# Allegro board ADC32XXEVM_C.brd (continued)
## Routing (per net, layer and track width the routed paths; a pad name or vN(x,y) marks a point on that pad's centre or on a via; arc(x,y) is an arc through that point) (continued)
A_INM: length 16.6
  TOP w0.483: R8.1 109.12,63.93 114.53,58.52 119.42,58.52 J2.1
A_INP: length 16.6
  TOP w0.483: J1.1 119.55,74.57 114.12,74.57 108.56,69.01 R4.1
ADCAM: length 23.3
  TOP w0.483: R121.1 v1(70.65,65.96)
  BOTTOM w0.216: v1(70.65,65.96) 71.06,66.37 72.57,66.37 75.35,69.15 75.35,73.22 77.67,75.54 80.1,75.54 81.55,74.09 R101.1
  BOTTOM w0.483: C181.2 84.61,75.01 ; 84.61,75.01 83.69,74.09 R101.1 ; 84.61,75.01 L24.2
ADCAP: length 23.3
  TOP w0.483: R120.2 v1(70.65,67.01)
  BOTTOM w0.216: v1(70.65,67.01) 70.92,66.74 72.41,66.74 74.98,69.3 74.98,73.37 77.52,75.91 80.25,75.91 80.26,75.9 81.51,77.14 R156.2
  BOTTOM w0.483: R156.2 83.67,77.14 84.53,76.28 C181.1 84.71,76.28 L23.2
ADCBM: length 23.3
  TOP w0.483: v1(50.93,65.96) R144.1
  BOTTOM w0.203: R154.2 38.28,74.07 39.65,75.44 40.59,75.44 44.53,71.51 44.53,70.52 48.75,66.29 50.7,66.29 50.93,66.07 v1(50.93,65.96)
  BOTTOM w0.483: R154.2 36.04,74.07 35.26,74.85 C206.1 34.19,75.01 L26.2
ADCBP: length 23.3
  TOP w0.483: v1(50.93,67.01) R141.2
  BOTTOM w0.203: v1(50.93,67.01) 50.57,66.65 48.9,66.65 44.88,70.66 44.88,71.65 40.74,75.79 39.62,75.79 38.3,77.11 R134.1
  BOTTOM w0.483: L27.2 34.24,76.02 C206.2 35.26,76.15 36.22,77.11 R134.1
AINM: length 6.1
  TOP w0.216: R14.2 68.47,66.33 65.23,66.33 65.16,66.27 U1.10
AINP: length 6.1
  TOP w0.216: U1.11 65.16,66.77 65.23,66.7 68.53,66.7 R3.2
AMPAINM: length 19.7
  TOP w0.216: R136.1 105.28,66.07 105.07,66.29 104.85,66.29 104.85,66.28 v1(104.55,65.98)
  BOTTOM w0.216: R97.2 104.33,75.52 104.33,76.21 104.57,76.45 105.23,76.45 106.48,75.21 106.48,71.48 103.42,68.42 103.42,66.71 103.85,66.28 104.25,66.28 v1(104.55,65.98)
  BOTTOM w0.483: R97.2 R96.1 R93.1
AMPAINP: length 19.7
  TOP w0.216: R135.2 105.28,66.87 105.07,66.66 104.84,66.66 v1(104.55,66.95)
  BOTTOM w0.216: v1(104.55,66.95) 104.25,66.65 104,66.65 103.78,66.87 103.78,68.26 106.85,71.32 106.85,75.36 105.39,76.82 104.56,76.82 104.34,77.04 104.34,77.67 103.91,78.11 R98.1
  BOTTOM w0.483: R92.1 101.5,78.11 R98.1
AMPBINM: length 19.7
  TOP w0.216: v1(17.29,66.11) 17.29,66.11 17.01,66.4 16.79,66.4 16.57,66.19 16.57,65.27 R138.1
  BOTTOM w0.216: R133.1 15.75,74.73 15.75,75.51 15.47,75.79 14.86,75.79 14.15,75.08 14.15,74.7 14.26,74.59 14.27,74.59 14.38,74.48 14.38,74.33 14.27,74.22 14.26,74.22 14.15,74.11 14.15,72.94 18.66,68.43 18.66,67.08 17.96,66.38 17.56,66.38 v1(17.29,66.11)
  BOTTOM w0.483: R127.1 R133.1
AMPBINP: length 19.7
  TOP w0.216: v1(17.29,67.07) 17.29,67.06 17.01,66.77 16.79,66.77 16.57,66.99 16.57,67.81 R137.2
  BOTTOM w0.216: v1(17.29,67.07) 17.61,66.75 17.81,66.75 18.29,67.23 18.29,68.28 13.78,72.78 13.78,75.24 14.71,76.16 15.51,76.16 15.72,76.38 15.72,77.32 R132.2
  BOTTOM w0.483: R128.1 R131.1 R132.2
B_INM: length 16.6
  TOP w0.483: R23.1 16.14,68.99 12.93,68.99 7.16,74.75 2.36,74.75 J3.1
B_INP: length 16.6
  TOP w0.483: R138.2 16.21,64.19 12.75,64.19 7.16,58.6 2.34,58.6 J4.1
BINM: length 6.1
  TOP w0.216: R144.2 53.1,66.33 56.34,66.33 56.4,66.27 U1.27
BINP: length 6.1
  TOP w0.216: R141.1 53.04,66.7 56.34,66.7 56.4,66.77 U1.26
CLKINM: length 11.9
  TOP w0.216: R61.1 62.74,72.64 63.07,72.3 63.07,71.81 62.01,70.75 61.84,70.75 60.59,69.51 60.59,68.1 U1.19
  TOP w0.483: T9.4 62.74,74.88 R61.1
CLKINP: length 11.8
  TOP w0.216: U1.18 60.96,68.11 60.96,69.35 61.99,70.38 62.17,70.38 63.36,71.58 63.79,71.58 64.2,71.17 64.8,71.17 R60.2
  TOP w0.483: T9.6 68.97,73.49 66.76,71.28 R60.2
CLOCK_INM: length 7.9
  TOP w0.483: C44.2 76.35,81.28 J10.1
CLOCK_INP: length 8
  TOP w0.483: C43.2 71.57,85 69.22,87.35 J9.1
DA0M: length 53.2
  TOP w0.216: J13.44 67.27,9.61 67.27,11.38 67.5,11.61 67.5,55.37 63.47,59.41 63.47,60.07 63.53,60.14 U1.48
DA0P: length 53.3
  TOP w0.216: U1.47 63.03,60.14 63.1,60.07 63.1,59.25 67.13,55.22 67.13,11.76 66.9,11.53 66.9,9.65 J13.46
DA1M: length 53.2
  TOP w0.216: J13.50 65.77,9.6 65.77,24.02 64.72,25.07 64.72,47.66 65.19,48.13 65.19,50.69 64.72,51.16 64.72,56.07 62.47,58.32 62.47,60.07 62.53,60.14 U1.46
DA1P: length 53.3
  TOP w0.216: U1.45 62.03,60.14 62.1,60.07 62.1,58.17 64.35,55.92 64.35,51 64.82,50.53 64.82,48.29 64.35,47.82 64.35,24.92 65.41,23.86 65.41,9.65 J13.52
DB0M: length 53.3
  TOP w0.216: J13.70 55.77,9.62 55.77,23.46 56.93,24.63 56.93,47.27 57.32,47.65 57.32,50.67 56.93,51.05 56.93,55.94 59.47,58.48 59.47,60.07 59.53,60.14 U1.40
DB0P: length 53.3
  TOP w0.216: U1.39 59.03,60.14 59.1,60.07 59.1,58.63 56.57,56.1 56.57,50.9 56.95,50.52 56.95,47.8 56.57,47.42 56.57,24.78 55.4,23.61 55.4,9.64 J13.72
DB1M: length 53.3
  TOP w0.216: U1.38 58.53,60.14 58.47,60.07 58.47,59.57 54.22,55.32 54.22,9.66 J13.76
DB1P: length 53.2
  TOP w0.216: U1.37 58.03,60.14 58.1,60.07 58.1,59.72 53.85,55.47 53.85,9.59 J13.78
DCLKM: length 53.3
  TOP w0.216: U1.44 61.53,60.14 61.47,60.07 61.47,57.62 62.22,56.87 62.22,52.84 61.93,52.54 61.93,51.01 62.31,50.63 62.31,48.81 62.09,48.6 62.09,46.73 62.51,46.31 62.51,44.9 62.22,44.61 62.22,23.95 64.25,21.92 64.25,9.63 J13.56
DCLKP: length 53.3
  TOP w0.216: J13.58 63.88,9.63 63.88,21.77 61.85,23.8 61.85,44.76 62.14,45.05 62.14,46.16 61.72,46.58 61.72,48.75 61.94,48.96 61.94,50.47 61.56,50.86 61.56,52.7 61.85,52.99 61.85,56.72 61.1,57.47 61.1,60.07 61.03,60.14 U1.43
FCLKM: length 53.3
  TOP w0.216: J13.64 57.26,9.62 57.26,21.34 59.61,23.69 59.61,46 59.3,46.31 59.3,47.73 59.61,48.05 59.61,50.53 59.3,50.85 59.3,52.76 59.61,53.07 59.61,56.79 60.47,57.65 60.47,60.07 60.53,60.14 U1.42
FCLKP: length 53.3
  TOP w0.216: U1.41 60.03,60.14 60.1,60.07 60.1,57.8 59.25,56.95 59.25,53.23 58.93,52.91 58.93,50.69 59.25,50.38 59.25,48.21 58.93,47.89 58.93,46.16 59.25,45.84 59.25,23.85 56.9,21.5 56.9,9.64 J13.66
FPGA_CSEL: length 77.1
  TOP w0.203: J13.115 v1(44.32,4.6)
  TOP w0.254: R70.1 v1(103.5,31.09)
  BOTTOM w0.203: v1(103.5,31.09) 103.5,23.09 89.71,9.3 49.5,9.3 46.86,6.65 46.86,6.07 45.42,4.62 44.35,4.62 v1(44.32,4.6)
FPGA_SCLK: length 74.6
  TOP w0.203: v1(43,4.85) 43,4.24 43.31,3.93 J13.119
  TOP w0.254: R67.1 v1(96.65,31.14)
  BOTTOM w0.203: v1(43,4.85) 43,5.23 43.84,6.07 43.84,6.48 47.88,10.52 47.88,11.4 48.74,12.27 89.46,12.27 96.65,19.46 v1(96.65,31.14)
FPGA_SDI: length 76.4
  TOP w0.203: J13.117 v1(43.81,5.18)
  TOP w0.254: R68.1 v1(101.22,31.17)
  BOTTOM w0.203: v1(43.81,5.18) 45.03,5.18 45.82,5.97 45.82,6.68 49.13,9.99 89.37,9.99 101.22,21.84 v1(101.22,31.17)
FPGA_SDO: length 74.8
  TOP w0.203: J13.113 v1(44.83,5.82)
  TOP w0.254: R69.1 v1(98.93,31.14)
  BOTTOM w0.203: v1(98.93,31.14) 98.93,20.8 89.72,11.59 48.85,11.59 48.34,11.07 48.34,11 48.33,10.99 48.33,10.59 48.34,10.58 48.34,10.26 44.73,6.65 44.73,5.92 v1(44.83,5.82)
FTDI_VCCIO1.8V: length 67.7
  TOP w0.483: v1(40.7,39.26) 39.87,39.26 FB7.1
  TOP w0.508: U2.4 v1(100.09,37.27)
  LYR3_PWR w0.483: v1(100.09,37.27) 95.94,33.12 72.12,33.12 67.55,37.69 66.6,37.69
  LYR3_PWR w0.508: v1(40.7,39.26) 41.12,38.84 51.08,38.84 52.22,37.69 66.6,37.69
PDA: length 6.1
  BOTTOM w0.305: U7.12 93.36,76.87 92.91,77.32 92.91,79.4 R107.2
  BOTTOM w0.483: R107.2 93.55,79.98 R108.2
  BOTTOM w0.508: R108.2 C188.2
PDB: length 5.3
  BOTTOM w0.305: R123.2 27.55,74.56 U10.12
  BOTTOM w0.483: R124.2 30.02,73.53 C200.2 28.65,73.56 R123.2
PDN: length 61.9
  TOP w0.203: U1.31 56.65,64.27 56.18,63.8 v1(55.6,63.8)
  BOTTOM w0.152: v1(55.6,63.8) 55.6,65.51 54.79,66.32 54.79,67.67 55.8,68.68 56.85,68.68 57.1,68.43 58.83,68.43 59.16,68.1 62.08,68.1 62.19,68.21 64.18,68.21 64.34,68.05 64.34,66.62 64.41,66.55 64.41,60.68 65.84,59.26 65.84,58.98 70,54.81 92.96,54.81 94.69,53.09 94.69,50.11 93.6,49.02
RESET: length 57.4
  TOP w0.152: v1(60.2,70.21) 59.53,69.54 U1.21
  BOTTOM w0.152: C168.1 99.31,57.51 70.89,57.51 68.78,59.61 68.78,68.16 66.7,70.25 66.7,70.51 65.74,71.48 63.02,71.48 61.75,70.21 v1(60.2,70.21)
  BOTTOM w0.305: C168.1 99.95,55.75 R58.1 100.1,53.49 SW1.1
SCLK: length 16
  TOP w0.254: R72.1 v1(95.63,32.05)
  BOTTOM w0.254: JP2.2 86.06,32.05 v1(95.63,32.05)
SDATA: length 12.7
  TOP w0.254: R71.1 v1(100.2,32.11)
  BOTTOM w0.254: v1(100.2,32.11) 99.49,32.11 98.04,33.55 92.3,33.55 JP3.2
SDOUT: length 14.3
  TOP w0.254: R73.1 v1(97.92,32.08)
  BOTTOM w0.254: v1(97.92,32.08) 97.21,32.08 96.44,32.84 89.2,32.84 JP5.2
SEN: length 11.1
  TOP w0.254: R74.1 v1(102.49,32.11)
  BOTTOM w0.254: JP4.2 95.53,34.26 99.62,34.26 101.78,32.11 v1(102.49,32.11)
SYSREF_INM: length 7.9
  TOP w0.483: C47.2 48.34,84.97 50.16,86.79 J12.1
SYSREF_INP: length 7.9
  TOP w0.483: C46.2 43.67,81.2 J11.1
SYSREFM: length 11.9
  TOP w0.216: R66.1 55.14,71.2 55.81,71.2 56.24,71.63 56.6,71.63 58.6,69.63 58.6,68.96 58.53,68.9 U1.23
  TOP w0.483: R66.1 54.89,71.09 53.16,71.09 50.96,73.29 T10.4
SYSREFP: length 11.9
  TOP w0.216: R64.2 57.24,72.63 56.87,72.26 56.87,71.88 58.97,69.79 58.97,68.96 59.03,68.9 U1.22
  TOP w0.483: T10.6 55.02,77.47 57.24,75.24 R64.2
U5_SENSE: length 8.5
  TOP w0.203: U5.3 v1(28.14,45.59)
  BOTTOM w0.203: 35.46,45.59 v1(28.14,45.59)
VAMPA: length 10.8
  LYR4_PWR w0.508: 95.71,70.92 95.71,71.78
  BOTTOM w0.305: U7.5 95.86,73.97 v1(95.99,73.84) ; v1(94.79,73.61) 94.86,73.68 U7.7 ; U7.6 95.36,73.68 v1(95.43,73.61) ; U7.8 94.36,73.99 v1(94.21,73.84)
  BOTTOM w0.381: C160.A v1(97.99,71.83) ; C160.A v1(98.37,72.52) ; C160.A v1(97.99,73.15) ; C160.B v1(95.96,73.15) ; C160.B v1(95.55,72.49) ; C160.B v1(95.91,71.88)
  BOTTOM w0.508: D3.2 v1(100.2,80.72) ; R107.1 v1(93.5,82.27) ; 91.41,80.77 v1(91.41,81.46) ; R150.2 v1(89,71.93)
VAMPB: length 9.6
  BOTTOM w0.305: U10.7 25.08,77.66 v1(25.2,77.77) ; v1(24.56,77.77) 24.58,77.75 U10.6 ; v1(23.95,77.62) 24.08,77.49 U10.5 ; U10.8 25.58,77.37 v1(25.81,77.6)
  BOTTOM w0.381: C210.A v1(23.75,79.88) ; C210.A v1(24.23,79.25) ; C210.A v1(23.72,78.61) ; C210.B v1(21.44,79.25) ; C210.B v1(21.97,79.91) ; C210.B v1(21.95,78.64)
  BOTTOM w0.508: v1(19.71,71.96) 19.71,71.25 D4.2 ; R122.2 v1(25.2,79.48) ; R152.2 v1(31.04,79.04) ; R123.1 v1(28.6,71.27)
VCM: length 111.9
  TOP w0.305: v1(57.76,69.01) 58.03,68.74 U1.24
  TOP w0.483: L6.2 v1(47.6,65.81) C11.2 ; L2.2 v1(73.96,65.79) 73.96,65.07 C4.2
  BOTTOM w0.305: R149.1 86.56,71.2 86.56,61.29 85.47,60.2 TP1.1 76.56,60.2 75.49,61.26 75.49,64.26 v1(73.96,65.79) 72.54,64.36 70.05,64.36 69.22,65.2 69.22,69.57 67.31,71.48 67.31,72.29 66.4,73.2 62.41,73.2 61.75,72.54 60.68,72.54 58.29,70.15 58.29,69.55 v1(57.76,69.01) 57.38,69.01 C42.1 55.83,70.56 54.53,70.56 ; 54.53,70.56 53.92,71.17 53.11,71.17 46.07,78.22 46.07,81.85 42.11,85.8 34.09,85.8 31.9,83.62 31.9,81.05 32.39,80.57 v1(32.39,79.12) ; 54.53,70.56 54.53,68.99 52.91,67.36 52.91,65.35 51.77,64.21 49.2,64.21 v1(47.6,65.81)
  BOTTOM w0.508: R104.1 v1(32.39,79.12)
VCM_AMPA: length 6.4
  BOTTOM w0.305: U7.9 93,75.37 C209.1
  BOTTOM w0.483: C209.1 91.14,73.51 R151.1 R150.1 88.98,73.53 R149.2
VCM_AMPB: length 6.7
  BOTTOM w0.305: U10.9 27.06,76.06 C189.1
  BOTTOM w0.483: C189.1 28.75,77.5 R153.1 R152.1 R104.2
N16255310: length 6.4
  TOP w0.483: T1.5 v1(97.87,66.47) T1.2
  BOTTOM w0.508: v1(97.87,66.47) 97.92,66.52 C5.2
N16255380: length 4.5
  TOP w0.483: T2.4 T1.6
N16255412: length 4.5
  TOP w0.483: T2.6 T1.4
N16255546: length 6.3
  TOP w0.483: T2.5 v1(87.88,66.47) T2.2
  BOTTOM w0.483: C6.2 v1(87.88,66.47)
N16275326: length 6.2
  TOP w0.483: T3.5 v1(23.64,66.52) T3.2
  BOTTOM w0.483: C12.2 v1(23.64,66.52)
N16275406: length 3
  TOP w0.483: T4.1 36.62,63.93 C14.1
N16275410: length 4.5
  TOP w0.483: T3.4 26.48,64 T4.6
N16275430: length 4.5
  TOP w0.483: T3.6 26.48,69.08 T4.4
N16275564: length 6.3
  TOP w0.483: T4.2 33.71,66.54 v1(33.7,66.53) 33.69,66.54 T4.5
  BOTTOM w0.483: C13.2 v1(33.7,66.53)
N17995731: length 3
  TOP w0.483: C7.1 85.03,63.94 T2.3
N18036747: length 3.6
  TOP w0.483: R4.2 T1.3
N18037025: length 3.6
  TOP w0.483: R8.2 T1.1
N18037341: length 3.5
  TOP w0.483: R20.1 20.67,64.03 20.79,63.91 T3.3
N18145356: length 2.2
  TOP w0.483: R62.1 72.95,77.88 72.92,77.88
N18145361: length 2.2
  TOP w0.483: C43.1 69.32,81.55 T9.3
N18152532: length 3
  TOP w0.483: C1.1 T2.1
N18152657: length 3
  TOP w0.483: C8.1 T4.3
N18154317: length 68.6
  TOP w0.152: U1.13 63.53,68.41 63.8,68.68 v1(64.11,68.68)
  BOTTOM w0.152: JP2.1 84.33,40.89 90.4,40.89 95.94,46.43 95.94,52.78 93.37,55.35 70.26,55.35 67.34,58.27 67.34,63.28 67.44,63.39 67.44,66.27 66.7,67.01 66.7,67.59 66.17,68.12 65.68,68.12 65.1,68.71 63.88,68.71 v1(64.11,68.68)
N18154319: length 67.8
  TOP w0.152: U1.16 61.98,68.1 61.98,68.71 63.07,69.8 64.34,69.8 v1(64.72,69.42)
  BOTTOM w0.152: v1(64.72,69.42) 64.92,69.42 65.76,68.58 66.27,68.58 67.06,67.79 67.06,67.26 67.77,66.55 67.77,58.67 70.51,55.93 93.45,55.93 96.44,52.93 96.44,46.23 90.3,40.08 87.45,40.08 JP5.1
N18154320: length 66.4
  TOP w0.152: U1.15 62.53,68.83 63.17,69.47 63.98,69.47 64.54,68.91 65.53,68.91 v1(66.04,69.42)
  BOTTOM w0.152: v1(66.04,69.42) 66.95,69.42 68.45,67.92 68.45,59.31 70.84,56.92 93.65,56.92 97.49,53.09 97.49,45.39 93.73,41.63 JP4.1
  BOTTOM w0.254: 95.86,38.61 JP4.1
N18154541: length 64.7
  TOP w0.152: v1(63.4,68.99) 63.27,68.99 63.03,68.75 U1.14
  BOTTOM w0.152: v1(63.4,68.99) 64.29,69.88 65.32,69.88 65.58,69.61 65.58,69.23 65.85,68.96 66.83,68.96 68.12,67.67 68.12,58.98 70.74,56.36 93.57,56.36 96.95,52.98 96.95,45.77 JP3.1
N18158256: length 7
  TOP w0.381: C51.1 103.38,46.34 C50.1 103.34,45.04 U2.20
  TOP w1.016: FB1.1 103.89,46.88 C51.1
N18158298: length 3.1
  TOP w0.254: R73.2 99.44,33.27 U2.3
N18158304: length 3.5
  TOP w0.254: U2.1 98.14,34.26 R72.2
N18158332: length 10.9
  TOP w0.483: J14.2 110.27,38.65 C53.1 107.98,38.48 105.94,40.52 U2.16
N18158362: length 2.6
  TOP w0.483: C54.1 105.29,44.84 U2.17
N18158372: length 9.3
  TOP w0.483: U2.15 106.59,41.27 108.15,39.7 C52.1 110.36,39.45 J14.3
N18158488: length 3.1
  TOP w0.254: R71.2 100.74,33.25 U2.5
N18172592: length 3.5
  TOP w0.483: 20.81,69.11 R25.1
N18176897: length 4.2
  TOP w0.483: R9.1 76.07,64.95 C3.2 ; C3.2 L2.1 ; C3.2 R5.2
N18176915: length 2.4
  TOP w0.483: R6.2 C2.1 72.59,66.98 L3.2
N18176926: length 2.4
  TOP w0.483: L3.1 72.49,65.96 C2.2 R10.1
N18176961: length 3.7
  TOP w0.483: R3.1 R6.1 R2.2
N18176965: length 3.7
  TOP w0.483: R14.1 R10.2 R13.2
N18176992: length 4
  TOP w0.483: R2.1 R5.1 R1.2 L1.1
N18176994: length 3.9
  TOP w0.483: R13.1 R9.2 77.29,63.93 R12.2 77.27,63.96 L4.1
N18177028: length 4
  TOP w0.483: C1.2 81.02,69.04 R1.1 L1.2
N18177046: length 3.9
  TOP w0.483: L4.2 78.28,63.96 R12.1 C7.2
N18177748: length 4.2
  TOP w0.483: C10.2 45.49,68.02 R21.2 ; C10.2 L6.1 ; C10.2 R22.1
N18177758: length 2.4
  TOP w0.483: L7.2 49.07,67.01 C9.1 R19.2
N18177777: length 2.4
  TOP w0.483: R24.1 C9.2 48.97,65.99 L7.1
N18177812: length 3.7
  TOP w0.483: R139.1 R19.1 R16.2
N18177816: length 3.7
  TOP w0.483: R142.1 R24.2 R27.2
N18177835: length 3.9
  TOP w0.483: R16.1 R21.1 45.46,69.03 R15.2 44.27,67.85 L5.1
N18177837: length 4
  TOP w0.483: L8.1 R26.2 R22.2 R27.1
N18177879: length 3.9
  TOP w0.483: C8.2 43.21,69.08 R15.1 43.28,69.01 L5.2
N18177897: length 3.9
  TOP w0.483: L8.2 R26.1 C14.2
N18182829: length 2.2
  TOP w0.483: 49.08,82.94 T10.1
N18182834: length 2.2
  TOP w0.483: C46.1 45.49,79.35 T10.3
N18184820: length 3.5
  TOP w0.305: U4.1 36.09,24.89 R80.1 37.34,23.88 R76.2
N18184826: length 4.3
  TOP w0.305: R77.2 R81.1 38.22,26.67 U4.3
N18184858: length 3.8
  TOP w0.305: L17.1 30.57,26.17 U4.7
N18184878: length 1
  TOP w0.508: R79.1 v1(38.23,31.37) ; R78.1 v1(38.23,30.23)
  vias: v1(31.24,32.38) v1(31.24,31.75) v1(31.24,31.12) v1(31.24,30.48) v1(31.24,29.84) v1(32,29.84)
N18184911: length 0.8
  TOP w0.305: U4.4 35.55,27.17 35.94,27.56
N18184929: length 1.3
  TOP w0.508: FB7.2 v1(33.73,40.41)
N18185106: length 2.7
  TOP w0.305: U5.14 v1(19.88,44.94)
  BOTTOM w0.508: v1(19.88,44.94) 19.96,44.86 C74.1
N18185155: length 1.7
  TOP w0.305: U5.12 v1(20.72,46.24)
  BOTTOM w0.508: v1(20.72,46.24) 20.86,46.1 R84.2
N18185175: length 1.9
  TOP w0.305: U5.11 20.95,46.89 v1(20.7,47.14)
  BOTTOM w0.508: v1(20.7,47.14) 20.8,47.24 R85.2
N18185416: length 8.1
  BOTTOM w0.508: TP8.1 40.92,33.88 R83.1 38.61,35.69 38.02,35.1 36.32,35.1 35.16,36.26 U6.1
N18185709: length 6.1
  TOP w0.508: Q1.4 21.59,27.3 20.32,28.57 20.32,31.12 19.36,32.07 U3.4
N18185817: length 2.9
  TOP w0.508: R75.2 21.97,29.21
N18186843: length 3.4
  TOP w0.305: U2.11 104.64,33.9 R74.2
N18187243: length 5.2
  TOP w0.305: J14.4 111.87,40.25 111.35,40.77 111.35,41.73 110.67,42.42 110.13,42.42 R86.1
N18187932: length 2.3
  BOTTOM w0.254: R87.2 106.58,53.52 SW1.2
N18195117: length 2.1
  TOP w0.635: 63.8,72.39 R61.2 ; 63.8,72.39 R60.1 ; 63.8,72.39 64.56,73.15 C45.1
N18195272: length 6.3
  TOP w0.508: T9.2 v1(69.18,77.74) T9.5
  BOTTOM w0.508: C173.1 69.18,77.67 v1(69.18,77.74)
N18195497: length 2.1
  TOP w0.635: 56.15,72.35 55.39,73.1 C48.1 ; 56.15,72.35 R64.1 ; 56.15,72.35 R66.2
N18195560: length 6.5
  TOP w0.508: T10.2 v1(50.75,77.68) 52.76,75.67
  BOTTOM w0.508: v1(50.75,77.68) 51.38,78.31 C174.1
N18236051: length 3.3
  BOTTOM w0.483: R109.2 90.17,76.3 C180.1 89.1,76.28 L23.1
N18236057: length 3.3
  BOTTOM w0.483: R110.2 90.42,75.29 C180.2 87.55,75.29 L24.1
N18238916: length 3.6
  BOTTOM w0.508: FB8.1 89.23,79.2 R106.1 91.41,77.93 C187.1
N18248026: length 2.3
  BOTTOM w0.305: U7.10 92.03,75.87 R110.1
N18248246: length 2.1
  BOTTOM w0.305: U7.11 91.67,76.37 R109.1
N18248498: length 4.5
  BOTTOM w0.305: R93.2 100.48,75.41 99.72,76.17 R95.2 98.96,75.87 U7.3
N18248506: length 2.6
  BOTTOM w0.305: R95.1 99.05,75.37 U7.4
N18248596: length 6.3
  BOTTOM w0.305: D3.3 100.46,78.24 R92.2 99.52,77.19 R94.2 98.45,76.37 U7.2
N18248639: length 3.1
  BOTTOM w0.305: R94.1 99.01,78.21 97.68,76.87 U7.1
N18255095: length 2.5
  TOP w0.305: C195.1 17.9,50.05 U8.14
N18255144: length 2.4
  TOP w0.305: R114.2 16.6,50.12 U8.12
N18255168: length 2.7
  TOP w0.305: R113.2 15.95,50.74 U8.11
N18255172: length 2.1
  TOP w0.305: U8.10 13.41,53.74 R116.2
N18255251: length 2.1
  TOP w0.508: U9.1 25.81,57.45 R115.1
N18258500: length 1.8
  TOP w0.305: R117.2 12.82,54.39 U8.9
N18258503: length 2.1
  TOP w0.305: U8.8 13.44,55.04 R118.2
N18258506: length 2.1
  TOP w0.305: R119.2 13.41,56.34 U8.6
N18271567: length 3
  BOTTOM w0.508: FB9.1 C199.1 R122.1
N18273924: length 3.1
  BOTTOM w0.483: R125.2 29.59,75.01 C205.1 32.41,75.01 32.51,74.9
N18273934: length 3.1
  BOTTOM w0.483: R126.2 29.64,76.02 C205.2 32.36,76.02 32.51,76.17
N18274097: length 2.3
  BOTTOM w0.305: U10.10 27.86,75.56 R126.1
N18274103: length 2.1
  BOTTOM w0.305: R125.1 28.32,75.06 U10.11
N18274115: length 4.6
  BOTTOM w0.305: U10.3 22.23,75.56 21.11,76.68 R130.2 20.52,76.68 R128.2
N18274119: length 3.2
  BOTTOM w0.305: R130.1 20.83,77.7 22.47,76.06 U10.4
N18274129: length 5.9
  BOTTOM w0.305: D4.3 20.64,73.24 R127.2 20.52,75.39 R129.2 21.31,75.39 21.64,75.06 U10.2
N18274135: length 2.6
  BOTTOM w0.305: R129.1 20.87,74.56 U10.1
N18283030: length 1.6
  BOTTOM w0.508: C207.1 102.59,72.44 SJP1.3
N18283930: length 1.8
  BOTTOM w0.483: R97.1 103.96,72.49 SJP1.2
N18284096: length 1.5
  BOTTOM w0.508: C208.1 18.97,80.7 SJP2.3
N18284104: length 2
  BOTTOM w0.508: SJP2.2 16.1,80.64 R132.1
N18358536: length 2.1
  BOTTOM w0.483: R155.1 36.42,75.59 ; 36.42,75.59 R134.2 ; 36.42,75.59 R154.1
N18359182: length 2.1
  BOTTOM w0.483: R101.2 83.41,75.62 ; 83.41,75.62 R156.1 ; 83.41,75.62 R157.1

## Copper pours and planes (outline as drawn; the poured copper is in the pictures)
1.8V on BOTTOM: 15.88,36.4 15.88,34.29 16.51,33.66 33.27,33.66 33.27,36.4
2.8V_IN on TOP: 16.26,39.88 16.26,45.85 22.35,45.85 22.35,43.56 23.24,43.56 23.24,42.16 20.96,39.88
5.0V_IN on TOP (solid shape): 20,23.14 16.19,23.14 16.19,27.66 20,27.66
5.0V_IN on TOP: 20.07,27.74 20.07,17.78 15.72,17.78 11.05,22.45 11.05,33.66 17.78,33.66 17.78,27.74
5.0V_IN on BOTTOM: 3.18,27.94 3.18,43.18 13.97,43.18 13.97,34.14 20.32,27.79 20.32,17.78 14.61,17.78 13.34,19.05 13.34,19.68 10.79,22.23 8.89,22.23
5.0V_IN on LYR2_GND, LYR3_PWR, LYR4_PWR, LYR5_GND: 16.89,27.81 16.89,22.99 20.07,22.99 20.07,27.81
5VIN on TOP: 31.29,20.7 31.29,23.39 32.84,24.94 32.84,25.55 33.02,25.73 33.73,25.73 33.78,25.68 33.78,23.32 32.97,22.5 32.97,20.7
5VIN on TOP: 24.89,21.97 24.89,24.13 25.53,24.13 25.53,25.91 25.65,25.91 25.65,29.59 27.94,29.59 27.94,27.3 26.8,27.3 26.8,21.97
5VIN on BOTTOM, LYR2_GND, LYR3_PWR, LYR5_GND: 25.91,29.21 25.91,27.3 28.19,27.3 28.19,29.21
5VIN on LYR4_PWR: 5.08,17.78 5.08,40 23.5,40 26.67,43.18 26.67,46.99 25.65,48.01 16.97,48.01 16.97,52.7 19.05,52.7 20.32,53.97 22.48,53.97 22.48,53.34 24.77,53.34 24.77,53.97 25.4,54.61 27.94,54.61 34.29,48.26 34.32,40 97.79,40 97.79,50.8 116.84,50.8 116.84,17.78
+VCC on TOP: 21.23,84.48 21.23,81.91 23.95,81.91 23.95,84.48
+VCC on TOP: 90.65,84.53 90.65,82.3 90.58,82.22 88.21,82.22 88.21,84.53
+VCC on BOTTOM: 21.21,84.43 21.21,81.99 23.62,81.99 24.16,82.52 25.25,82.52 25.25,84.43
+VCC on BOTTOM: 20.83,55.63 20.83,54.86 21.84,53.85 24.26,53.85 24.26,54.61 23.24,55.63
+VCC on BOTTOM: 90.78,82.45 90.78,84.58 88.29,84.58 88.29,80.85 89.94,80.85 89.94,81.61
+VCC on LYR2_GND, LYR3_PWR, LYR5_GND: 20.96,84.45 20.96,81.91 23.75,81.91 23.75,84.45
+VCC on LYR2_GND, LYR3_PWR, LYR5_GND: 90.45,85.9 90.45,83.67 90.37,83.59 88.01,83.59 88.01,85.9
+VCC on LYR4_PWR: 92.07,84.12 89.87,81.91 88.16,81.91 87.58,82.5 87.58,85.19 86.87,85.9 78.49,85.9 78.33,85.75 78.33,79.22 42.42,79.22 42.42,84.53 41.1,85.85 33.38,85.85 31.75,84.45 31.75,81.28 20.96,81.28 15.88,76.2 15.88,67.69 17.91,65.66 17.91,57.78 2.54,57.78 2.54,95.88 92.07,95.88
AVDD1.8V on TOP, LYR2_GND, LYR3_PWR, LYR5_GND: 41.2,54.69 44.48,54.69 44.63,54.53 44.63,52.1 44.42,51.89 42.77,51.89 42.67,51.99 42.67,53.16 42.37,53.47 41.25,53.47 41.07,53.64 41.07,54.56
AVDD1.8V on BOTTOM: 41.33,51.71 41.33,54.71 44.6,54.71 44.6,51.71
AVDD1.8V on LYR4_PWR: 35.81,50.8 35.81,74.8 69.22,74.8 69.22,63.37 65.76,63.37 65.38,63.75 47.37,63.75 46.99,63.37 46.99,50.8
DVDD1.8V on TOP, LYR2_GND, LYR4_PWR, LYR5_GND: 42.37,48.56 44.37,48.56 44.68,48.26 44.68,45.77 44.48,45.57 41.58,45.57 41.3,45.85 41.3,46.28 41.5,46.48 42.19,46.48 42.29,46.58 42.29,48.49
DVDD1.8V on BOTTOM: 41.38,48.46 41.38,45.62 44.6,45.62 44.6,48.46
DVDD1.8V on LYR3_PWR: 39.37,40.64 39.37,49.53 47.62,49.53 47.62,63.32 65.35,63.32 66.57,62.1 116.84,62.1 116.84,51.44 97.16,51.44 97.16,40.64
GND on TOP: 0.25,96.95 0.25,12.95 23.11,12.95 23.11,0.25 98.81,0.25 98.81,12.95 121.67,12.95 121.67,96.95 ; 18 cut-outs
GND on BOTTOM: 0.25,96.95 0.25,12.95 23.11,12.95 23.11,0.25 98.81,0.25 98.81,12.95 121.67,12.95 121.67,96.95 ; 3 cut-outs
GND on LYR2_GND, LYR3_PWR, LYR4_PWR, LYR5_GND: 0.25,96.95 0.25,12.95 23.11,12.95 23.11,0.25 98.81,0.25 98.81,12.95 121.67,12.95 121.67,96.95
CLKINM on TOP (solid shape): 66.63,77.88 66.99,77.88 67.35,78.24 67.44,78.33 67.94,77.83 67.28,77.16 65.91,77.16 65.37,76.62 64.48,77.52 65.5,78.55 65.54,78.55 65.75,78.76
CLKINP on TOP (solid shape): 69.77,76 69.32,75.55 69.32,75.19 70.21,74.31 68.95,73.05 68.07,73.93 68.61,74.47 68.61,75.83 69.27,76.5
SYSREFM on TOP (solid shape): 50.75,76.35 51.32,75.78 51.32,74.41 51.86,73.87 50.96,72.98 49.94,74 49.94,74.04 49.72,74.25 50.6,75.13 50.6,75.49 50.24,75.85 50.15,75.94 50.66,76.44
SYSREFP on TOP (solid shape): 55.43,77.45 55.24,77.25 54.56,76.57 54.02,77.11 52.65,77.11 51.99,77.77 52.49,78.27 52.94,77.83 53.3,77.83 54,78.53 54.18,78.71
U5_SENSE on BOTTOM: 36.53,37.9 36.53,42.82 35.31,44.04 35.31,53.59 39.12,53.59 39.12,38.25 38.76,37.9
VAMPA on LYR4_PWR: 102.64,79.6 102.64,72.42 100.84,70.61 87.53,70.61 87.53,78.51 91.82,82.8 99.44,82.8
VAMPB on LYR4_PWR: 33.53,70.87 17.4,70.87 17.4,76.33 21.72,80.64 30.15,80.64 33.53,77.27
N16255310 on TOP (solid shape): 96.27,66.85 97.16,66.85 97.16,66.09 96.27,66.09 96.01,65.84 95.83,65.84 95.83,66.09 94.49,66.09 94.49,66.85 95.83,66.85 95.83,67.11 96.01,67.11
N16255310 on TOP (solid shape): 100.76,67.08 100.76,66.85 101.35,66.85 101.35,66.09 100.86,66.09 100.86,65.84 99.82,65.84 99.57,66.09 98.68,66.09 98.68,66.85 99.57,66.85 99.82,67.11 100.74,67.11
N16255380 on TOP (solid shape): 97.16,64.8 96.52,64.8 96.27,64.54 96.27,63.3 94.49,63.3 94.49,64.54 95.25,64.54 96.22,65.51 97.16,65.51
N16255380 on TOP (solid shape): 90.49,64.54 91.25,64.54 91.25,63.27 89.8,63.27 89.78,63.3 89.47,63.3 89.47,64.54 89.22,64.8 88.59,64.8 88.59,65.51 89.52,65.51
N16255412 on TOP (solid shape): 91.25,68.4 90.49,68.4 89.52,67.44 88.59,67.44 88.59,68.15 89.22,68.15 89.47,68.4 89.47,69.65 91.25,69.65
N16255412 on TOP (solid shape): 95.96,69.65 96.27,69.65 96.27,68.4 96.52,68.15 97.16,68.15 97.16,67.44 96.22,67.44 95.25,68.4 94.49,68.4 94.49,69.67 95.94,69.67
N16255546 on TOP (solid shape): 89.91,66.85 91.25,66.85 91.25,66.09 89.91,66.09 89.91,65.84 89.73,65.84 89.47,66.09 88.59,66.09 88.59,66.85 89.47,66.85 89.73,67.11 89.91,67.11
N16255546 on TOP (solid shape): 86.17,66.85 87.06,66.85 87.06,66.09 86.17,66.09 85.92,65.84 85,65.84 84.98,65.86 84.98,66.09 84.39,66.09 84.39,66.85 84.88,66.85 84.88,67.11 85.92,67.11
N16275326 on TOP (solid shape): 25.74,66.9 27.09,66.9 27.09,66.14 25.74,66.14 25.74,65.88 25.57,65.88 25.31,66.14 24.42,66.14 24.42,66.9 25.31,66.9 25.57,67.15 25.74,67.15
N16275326 on TOP (solid shape): 22.01,66.9 22.9,66.9 22.9,66.14 22.01,66.14 21.76,65.88 20.84,65.88 20.82,65.91 20.82,66.14 20.23,66.14 20.23,66.9 20.71,66.9 20.71,67.15 21.76,67.15
N16275406 on TOP (solid shape): 36.45,64.61 37.13,64.61 37.16,64.58 37.16,63.39 35.41,63.39 35.41,64.64 35.15,64.89 34.52,64.89 34.52,65.6 35.46,65.6
N16275410 on TOP (solid shape): 32.99,64.89 32.36,64.89 32.1,64.64 32.1,63.39 30.33,63.39 30.33,64.64 31.09,64.64 32.05,65.6 32.99,65.6
N16275410 on TOP (solid shape): 26.33,64.61 27.09,64.61 27.09,63.34 25.64,63.34 25.62,63.37 25.31,63.37 25.31,64.61 25.06,64.87 24.42,64.87 24.42,65.58 25.36,65.58
N16275430 on TOP (solid shape): 27.09,68.42 26.33,68.42 25.36,67.46 24.42,67.46 24.42,68.17 25.06,68.17 25.31,68.42 25.31,69.67 27.09,69.67
N16275430 on TOP (solid shape): 31.8,69.69 32.1,69.69 32.1,68.45 32.36,68.19 32.99,68.19 32.99,67.48 32.05,67.48 31.09,68.45 30.33,68.45 30.33,69.72 31.77,69.72
N16275564 on TOP (solid shape): 32.1,66.92 32.99,66.92 32.99,66.16 32.1,66.16 31.85,65.91 31.67,65.91 31.67,66.16 30.33,66.16 30.33,66.92 31.67,66.92 31.67,67.18 31.85,67.18
N16275564 on TOP (solid shape): 36.6,67.15 36.6,66.92 37.18,66.92 37.18,66.16 36.7,66.16 36.7,65.91 35.66,65.91 35.41,66.16 34.52,66.16 34.52,66.92 35.41,66.92 35.66,67.18 36.57,67.18
N17995731 on TOP (solid shape): 87.06,64.82 86.43,64.82 86.17,64.57 86.17,63.32 84.42,63.32 84.42,64.54 85.13,64.54 86.12,65.53 87.06,65.53
N18036747 on TOP (solid shape): 101.32,68.43 100.61,68.43 99.62,67.44 98.68,67.44 98.68,68.15 99.31,68.15 99.57,68.4 99.57,69.65 101.32,69.65
N18037025 on TOP (solid shape): 100.61,64.52 101.3,64.52 101.32,64.49 101.32,63.3 99.57,63.3 99.57,64.54 99.31,64.8 98.68,64.8 98.68,65.51 99.62,65.51
N18037341 on TOP (solid shape): 22.9,64.87 22.26,64.87 22.01,64.61 22.01,63.37 20.26,63.37 20.26,64.59 20.97,64.59 21.96,65.58 22.9,65.58
N18145356 on TOP (solid shape): 73.78,77.88 72.54,76.64 72.29,76.89 71.66,77.52 71.3,77.52 70.85,77.07 70.35,77.58 71.01,78.24 72.41,78.24 72.9,78.73 72.94,78.73
N18145361 on TOP (solid shape): 70.19,81.47 69.68,80.97 69.68,79.57 69.02,78.91 68.52,79.41 68.97,79.86 68.97,80.22 68.09,81.1 69.32,82.34
N18152532 on TOP (solid shape): 86.17,68.4 86.43,68.15 87.06,68.15 87.06,67.44 86.12,67.44 85.13,68.43 84.44,68.43 84.42,68.45 84.42,69.65 86.17,69.65
N18152657 on TOP (solid shape): 37.16,68.47 36.45,68.47 35.46,67.48 34.52,67.48 34.52,68.19 35.15,68.19 35.41,68.45 35.41,69.69 37.16,69.69
N18172592 on TOP (solid shape): 22.01,68.42 22.26,68.17 22.9,68.17 22.9,67.46 21.96,67.46 20.97,68.45 20.28,68.45 20.26,68.47 20.26,69.67 22.01,69.67
N18182829 on TOP (solid shape): 51.84,81.04 51.59,80.79 50.96,80.16 50.96,79.8 51.41,79.35 50.91,78.85 50.24,79.51 50.24,80.91 49.76,81.4 49.76,81.44 50.6,82.28
N18182834 on TOP (solid shape): 47.51,78.18 48.92,78.18 49.58,77.52 49.08,77.02 48.63,77.47 48.27,77.47 47.39,76.59 46.15,77.83 47.01,78.69
N18184858 on TOP: 28.19,25.02 28.19,26.29 33.66,26.29 33.66,26.04 32.64,26.04 31.75,25.15 31.75,25.02
N18184878 on TOP: 28.45,27.05 28.45,29.46 28.7,29.72 28.7,32.77 32.51,32.77 32.51,29.72 33.76,29.72 33.76,27.05
N18184878 on LYR3_PWR: 38.73,32.77 38.73,29.46 30.48,29.46 30.48,32.77
N18184911 on TOP: 35.08,27.18 35.08,27.94 36.07,27.94 36.32,28.19 36.32,31.75 37.08,31.75 37.08,27.43 36.83,27.18
N18184929 on BOTTOM: 35.56,37.16 35.56,41.15 33.91,42.8 33.91,42.82 30.12,42.82 29.46,42.16 29.46,37.16
N18184992 on TOP: 20.93,17.91 20.93,26.42 23.06,26.42 23.06,21.08 26.54,21.08 26.54,17.91
N18185086 on TOP: 32.39,39.88 32.39,41.66 29.97,41.66 29.72,41.91 29.72,44.58 26.42,44.58 26.42,43.56 25.4,43.56 25.4,39.93 29.24,39.93 29.29,39.88
N18185335 on TOP: 24.13,30.48 24.13,33.66 20.8,36.98 16.51,36.98 16.51,39.24 22.35,39.24 26.14,35.46 26.14,30.48
N18185335 on BOTTOM: 16.13,39.12 16.13,37.08 20.96,37.08 20.96,39.12
N18195272 on TOP (solid shape): 68.88,76.89 68.25,76.27 68.25,75.91 68.12,75.78 67.94,75.96 66.99,75.01 66.45,75.55 67.4,76.5 67.22,76.68 67.35,76.8 67.71,76.8 68.34,77.43
N18195272 on TOP (solid shape): 71.84,79.86 71.5,79.52 71.68,79.34 70.94,78.6 70.58,78.6 69.95,77.97 69.41,78.51 70.04,79.14 70.04,79.5 70.69,80.14 70.73,80.14 70.89,79.98 71.3,80.4
N18195560 on TOP (solid shape): 52.22,76.75 52.58,76.75 52.7,76.62 52.53,76.44 53.48,75.49 52.94,74.95 51.99,75.9 51.81,75.72 51.68,75.85 51.68,76.21 51.05,76.84 51.59,77.38
N18195560 on TOP (solid shape): 48.97,80 49.15,80.18 49.89,79.44 49.89,79.08 50.06,78.9 50.51,78.45 49.98,77.92 49.53,78.36 49.35,78.54 48.99,78.54 48.97,78.56 48.34,79.19 48.34,79.23 48.5,79.39 48.09,79.8 48.63,80.34
N18254985 on TOP: 18.31,57.18 18.31,59.13 18.11,59.13 18.11,62.03 20.07,62.03 20.07,60.45 24.16,60.45 24.16,56.16 19.3,56.16 19.3,57.18

Small or netless copper shapes (teardrops, artwork), in the pictures only: 2 on BOTTOM

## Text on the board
BOTTOM: LAYER 6 - BOTTOM SIDE
Board Geometry/Soldermask Bottom: SOLDERMASK BOTTOM
Ref Des/Silkscreen Bottom: SILKSCREEN BOTTOM | AC | DC
User.Comments: 2 | 1 | 60 | 59 | ON | K | 120 | 119 | 62 | 61 | * | 7 | 6 | 12 | DDR2 STD | 1.8V | 3 | 4 | SJP1 | C160 | C210 | SJP2 | R87 | R92 | R93 | C207 | D3 | C168 | R58 | U7 | R109 | R110 | C187 | L23 | L24 | R157 | C169 | C33 | C36 | C37 | C40 | C170 | C41 | C32 | C38 | C39 | C31 | C30 | C29 | C42 | R155 | FB5 | FB4 | U6 | RS1 | L27 | L26 | C200 | R124 | R126 | R125 | R122 | C199 | FB9 | U10 | R85 | R84 | C74 | D4 | R127 | R128 | R133 | D2 | R97 | R96 | R98 | R94 | C5 | R95 | R57 | C188 | R108 | R107 | C209 | R151 | FB8 | C180 | R150 | C6 | R149 | C181 | R101 | R156 | C173 | C35 | C34 | R83 | R154 | R134 | C206 | C13 | R104 | C72 | R152 | C205 | R153 | C66 | R123 | C189 | C12 | R129 | C64 | R130 | C65 | C208 | R131 | R132 | R106 | C174 | TEXAS INSTRUMENTS | TSW1400 REV D | ADC32XXEVM REV C | 18. | 19. | TOP AND BOTTOM LAYERS 8.5 MIL TRACES WITH 6.5 MIL SPACING TO BE 100 OHM DIFFERENTIAL IMPEDANCE. | PCB MUST BE RoHS COMPLIANT AND SURVIVE LEAD FREE ASSEMBLY, | MAX REFLOW OF 260 DEGREES C (6 PASSES). | ALL 6 MIL, 8 MIL AND 10 MIL HOLES/VIAS TO BE PLATED AND FILLED WITH NON-CONDUCTIVE | EPOXY. FILLED VIAS SHALL BE PLATED AFTER FILLING AND COPLANAR. | ASSEMBLY TOP | ASSEMBLY BOTTOM
TOP: LAYER 1 - TOP SIDE
Board Geometry/Soldermask Top: SOLDERMASK TOP
Ref Des/Silkscreen Top: GND | SILKSCREEN TOP | DC/DC | LDO | LO | HI | MASTER | DUT | PCB REV C | ADC32    EVM | BINP | BINM | 5V IN | AINP | AINM
LYR2_GND: LAYER 2 - GROUND PLANE
LYR3_PWR: LAYER 3 - POWER PLANE
LYR4_PWR: LAYER 4 - POWER PLANE
LYR5_GND: LAYER 5 - GROUND PLANE
DIMENSION: PASTEMASK TOP
PAGE_OUTLINE: PASTEMASK BOTTOM
User.11: OFF | SCREW | STAND | L NGUYEN | K CHAN | 07-08-14 | 2.  FINISHED ASSEMBLY MUST BE LEAD FREE AND RoHS COMPLIANT. | 3.  REMOVE METAL TAB ON BOTH BANANA JACKS BEFORE MOUNTING ON THE BOARD. | USE LOCTITE THREADLOCKER BLUE 242 (OR EQUIVALENT) WHEN INSTALLING | THE BANANA JACKS.
User.21: FIGURE | SIZE | 8.0 | 10.0 | 12.0 | 38.0 | 40.0 | 55.0 | 62.0 | 67.0 | 68.0 | 120.0 | 125.0 | 140.0 | 35.0 | DRILL CHART: TOP to BOTTOM | ALL UNITS ARE IN MILS | PLATED | NON-PLATED | QTY | 8 | 1764 | 185 | 1 | 17 | 2 | 10 | 16 | 4
